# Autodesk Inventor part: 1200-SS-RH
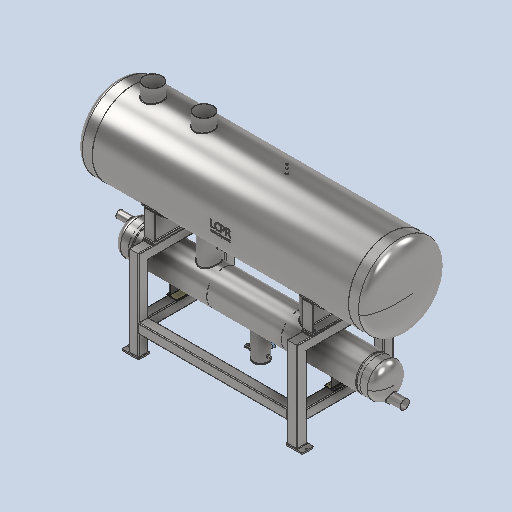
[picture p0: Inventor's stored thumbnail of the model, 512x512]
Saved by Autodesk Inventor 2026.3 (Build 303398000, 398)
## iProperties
Created: 2026-05
Part Number: 1200-SS-RH
Material: Generic
Document SubType Name: Modeling
Designer: rva
Density: 1 g/cm^3
Appearance: Default
Author: rva
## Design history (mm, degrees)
derived "LCPR-SS-1200-RH.iam"
body "Solid1"
node "Sub-SS-500-250-3326-294-125-100-RH.iam:1::LCPR-SS-500 mm Sub"
node "Sub-SS-500-250-3326-294-125-100-RH.iam:1::LCPR-SS-500 mm Sub"
node "Sub-SS-500-250-3326-294-125-100-RH.iam:1::H1100-R.ipt:1"
node "Sub-SS-500-250-3326-294-125-100-RH.iam:1::1-2 Inch NPT Socke"
node "Sub-SS-500-250-3326-294-125-100-RH.iam:1::Welds"
node "LCPR-SS-1200-Frame Assembly.iam:1::LCPR-SS_170 x 250 Foot Pl"
node "LCPR-SS-1200-Frame Assembly.iam:1::LCPR-SS_170 x 250 Foot Pl"
node "LCPR-SS-1200-Frame Assembly.iam:1::LCPR-SS_170 x 250 Foot Pl"
node "LCPR-SS-1200-Frame Assembly.iam:1::LCPR-SS_170 x 250 Foot Pl"
node "LCPR-SS-1200-Frame Assembly.iam:1::Welds"
node "AS 1112 - M20(2).ipt:1"
node "AS 1237 (4.2) 20 mm:1"
node "AS 1111 - Metric M20 x 200:1"
node "AS 1112 - M20(2).ipt:2"
node "AS 1237 (4.2) 20 mm:3"
node "AS 1111 - Metric M20 x 200:2"
node "AS 1112 - M20(2).ipt:3"
node "AS 1237 (4.2) 20 mm:5"
node "AS 1111 - Metric M20 x 200:3"
node "AS 1112 - M20(2).ipt:4"
node "AS 1237 (4.2) 20 mm:7"
node "AS 1111 - Metric M20 x 200:4"
node "Nylon Heat Tranfer Spacer 1028 x 150.ipt:1"
node "Nylon Heat Tranfer Spacer 1028 x 150.ipt:2"
node "LCPR-SS-1200-3800-250-WELD.iam:1::ASME B36.10M Pipe 48x0.375"
node "LCPR-SS-1200-3800-250-WELD.iam:1::LCPR-LOGO.ipt:1"
node "LCPR-SS-1200-3800-250-WELD.iam:1::H1100-R.ipt:1"
node "LCPR-SS-1200-3800-250-WELD.iam:1::1200 mm-SS-Dome End Cap S1"
node "LCPR-SS-1200-3800-250-WELD.iam:1::LCPR-SS-1200-Leg Assembly."
node "LCPR-SS-1200-3800-250-WELD.iam:1::LCPR-SS-1200-Leg Assembly."
node "LCPR-SS-1200-3800-250-WELD.iam:1::1200 mm-SS-Dome End Cap S1"
node "LCPR-SS-1200-3800-250-WELD.iam:1::Welds"
node "Nylon Heat Tranfer Spacer 300 x 150.ipt:1"
node "Nylon Heat Tranfer Spacer 300 x 150.ipt:2"
node "LCPR-SS-1200-RH.iam_Bodies"
